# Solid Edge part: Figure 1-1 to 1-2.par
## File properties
Author: CADCIM
Template: normal.par
Last saved by: SOFT
Revision: 23
Application: Solid Edge
Accuracy: 0.99
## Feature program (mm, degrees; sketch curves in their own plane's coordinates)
sketch for "unnamed Protrusion 1" plane through (0, 0, 0) normal (0, 0, 1) x-axis (1, 0, 0)
  line (-63.0032, 49) -> (-56, -71)
  line (-56, -71) -> (56, -71)
  line (56, -71) -> (63.0032, 49)
  line (63.0032, 49) -> (0, 54)
  line (0, 54) -> (-63.0032, 49)
  dimension (linear) = 56
  dimension (linear) = 56
extrude "unnamed Protrusion 1" add finite 4 along +normal
fillet "Round_1" radius 15
sketch for "ExtrudedProtrusion_3" plane through (0, -8.5, 0) normal (0, 0, -1) x-axis (-1, 0, 0)
extrude "ExtrudedProtrusion_3" add finite 12 along -normal
pattern "unnamed Pattern 1" of "ExtrudedProtrusion_3"
pattern "unnamed Pattern 2"
sketch for "unnamed Protrusion 2" plane through (-1.0316, 2.3101, 4) normal (0, 0, 1) x-axis (-1, 0, 0)
extrude "unnamed Protrusion 2" add finite 5 along +normal
sketch for "Hole_22" plane through (40.9331, -54.9887, 12) normal (0, 0, 1) x-axis (1, 0, 0)
  hole centre (-0.4331, -0.0113) bore radius 4.5
hole "Hole_22" diameter 9 through  CounterBoreDepth = 5 mm
pattern "unnamed Pattern 3" of "Hole_22"
hole "unnamed Hole 1" through
hole "unnamed Hole 2" through
hole "unnamed Hole 3" through
sketch for "Hole_29" plane through (-1.0316, -6.1899, 9) normal (0, 0, 1) x-axis (1, 0, 0)
  hole centre (0, 0) bore radius 11
hole "Hole_29" diameter 22 through
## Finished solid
Body 1: solid body, 34 faces, 55 edges, 18 vertices.
  Faces by surface: cylinder 18, plane 16
  Edges by curve: circle 36, line 19
Bounding box of the edges (mm): 124.346 x 125.000 x 12.000, from (-62.1729, -71, 0) to (62.1729, 54, 12).
Cylindrical faces by radius (mm): R4.5 x4, R7.5 x4, R10.7006 x4, R11 x1, R15 x4, R20 x1
Planar faces by outward normal: +z 10, -y 1, -z 1, oblique 4
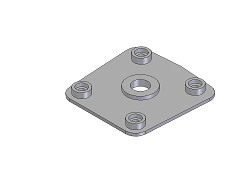
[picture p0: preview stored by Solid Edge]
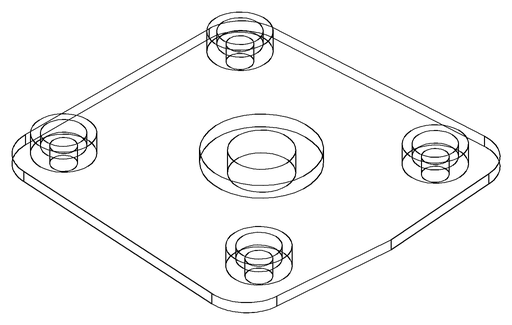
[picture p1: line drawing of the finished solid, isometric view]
